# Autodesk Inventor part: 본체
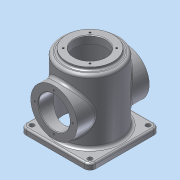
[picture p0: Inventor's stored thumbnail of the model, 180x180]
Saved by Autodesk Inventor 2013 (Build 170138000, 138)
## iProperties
Created: 2015-10
Part Number: 본체
Material: 알루미늄 6061
Document SubType Name: Modeling
Designer: dgall
Density: 2.71 g/cm^3
Mass: 987.031 g
Surface Area: 1039.62 cm^2
Volume: 364.218 cm^3
Author: dgall
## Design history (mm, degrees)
sketch "스케치1"
  geometry: L1 (-60, 60)-(60, 60); L2 (60, 60)-(60, -60); L3 (60, -60)-(-60, -60); L4 (-60, -60)-(-60, 60); L5 (-60, 60)-(60, -60); L6 (60, 60)-(-60, -60); C1 r 4 at (-50, 50); C2 r 4 at (50, 50); C3 r 4 at (50, -50); C4 r 4 at (-50, -50); 1 further point
  constraints: 12 end point, 4 centre point, 3 equal radius, 2 horizontal alignment, 2 midpoint, 2 parallel, 2 perpendicular, 2 vertical alignment, 1 horizontal
  dimensions: "d0" = 120 distance of L2.end L3.end; "d1" = 8 diameter of C1; "d2" = 100 distance of C2.centre C1.centre; "d3" = 50 horizontal distance of point (0, 0) C1.centre; "d4" = 100 distance of C3.centre C2.centre; "d5" = 50 horizontal distance of point (0, 0) C3.centre
extrude "돌출1" new body sketch "스케치1" distance "d6" = 10; taper "d7" = 0 deg
sketch "스케치2"
  geometry: C1 r 50 at (0, 0); C2 r 27 at (0, 0); 1 further point
  constraints: 2 centre point, 2 coincident
  dimensions: "d8" = 100 diameter of C1; "d9" = 54 diameter of C2
extrude "돌출2" join sketch "스케치2" distance "d10" = 115; taper "d11" = 0 deg
sketch "스케치4"
  geometry: C1 r 45 at (0, 0); 1 further point
  constraints: 1 centre point, 1 coincident
  dimensions: "d25" = 90 diameter of C1
extrude "돌출4" cut sketch "스케치4" distance "d26" = 112; taper "d27" = 0 deg
sketch "스케치5"
  geometry: C1 r 50 at (0, 0) reference; C2 r 50 at (0, 0); C3 r 40 at (0, 0)
  constraints: 2 centre point, 2 coincident
  dimensions: "d28" = 100 diameter of C2; "d29" = 80 diameter of C3
extrude "돌출5" cut sketch "스케치5" distance "d30" = 5; taper "d31" = 0 deg
fillet "모깎기1" dims "d32" = 10
sketch "스케치6"
  geometry: C1 r 4 at (-50, 50); C2 r 4 at (50, 50); C3 r 4 at (50, -50); C4 r 4 at (-50, -50); A1 r 10 centre (-50, 50) between (-50, 60) and (-60, 50) reference; A2 r 10 centre (-50, -50) between (-60, -50) and (-50, -60) reference; A3 r 10 centre (50, -50) between (50, -60) and (60, -50) reference; A4 r 10 centre (50, 50) between (60, 50) and (50, 60) reference
  constraints: 4 centre point, 4 coincident, 1 equal radius
  dimensions: "d33" = 8 diameter of C1; "d34" = 8 diameter of C3; "d35" = 8 diameter of C4
hole "구멍2" sketch "스케치6" at (-50, -50), (50, 50), (50, -50), (-50, 50) diameter "d36" = 8; stored, may be unused: countersink angle "d40" = 90 deg, drill point angle "d42" = 118 deg; dims "d37" = 6, "d38" = 4, "d39" = 2, "d41" = 8
fillet "모깎기2" dims "d43" = 5
sketch "스케치7"
  geometry: L1 (0, 100)-(0, 0) reference; 3 further points
  constraints: 1 horizontal alignment, 1 midpoint, 1 other
  dimensions: "d44" = 70 distance of point (0, 50) point (-70, 50)
feature "엠보싱1" sketch "스케치7" dims "d0" = 120, "d27" = 0, "d45" = 0.5, "d46" = 0
hole "구멍3" diameter "d52" = 54; stored, may be unused: countersink angle "d56" = 90 deg, drill point angle "d58" = 118 deg; dims "d50" = 10, "d51" = 10, "d53" = 6, "d54" = 4, "d55" = 2, "d57" = 8
sketch "스케치9"
  geometry: L1 (0, 0)-(-32.5, 0); L2 (0, 0)-(-22.981, -22.981); C1 r 40 at (0, 0) reference; A1 r 32.5 centre (0, 0) between (-32.5, 0) and (-22.981, -22.981); 1 further point
  constraints: 4 end point, 2 coincident, 2 point on circle, 1 centre point, 1 horizontal
  dimensions: "d60" = 65 diameter of A1; "d61" = 45 deg angle of L1 L2
hole "구멍4" sketch "스케치9" at (-22.981, -22.981) diameter "d63" = 3.242; stored, may be unused: countersink angle "d67" = 90 deg, drill point angle "d69" = 118 deg; dims "d64" = 8, "d65" = 4, "d66" = 2, "d68" = 10
sketch "스케치8"
  geometry: C1 r 40 at (0, 60); C2 r 27 at (0, 60); 1 further point
  constraints: 2 centre point, 1 concentric, 1 vertical alignment
  dimensions: "d47" = 80 diameter of C1; "d48" = 54 diameter of C2; "d49" = 60 distance of point (0, 0) C1.centre
extrude "돌출6" join sketch "스케치8" stored distance "d73" = 124; taper "d74" = 0 deg
extrude "돌출7" cut sketch "스케치8" stored distance "d75" = 124; taper "d76" = 0 deg
fillet "모깎기4" dims "d77" = 5
sketch "스케치10"
  geometry: L1 (0, 0)-(0, -32.5); C1 r 40 at (0, 0) reference; 2 further points
  constraints: 2 end point, 1 coincident, 1 vertical
  dimensions: "d78" = 32.5 distance of L1.start L1.end
hole "구멍5" sketch "스케치10" at (0, -32.5) diameter "d79" = 3.242; stored, may be unused: countersink angle "d83" = 90 deg, drill point angle "d85" = 118 deg; dims "d80" = 8, "d81" = 4, "d82" = 2, "d84" = 10
sketch "스케치11"
  geometry: L1 (0, 0)-(0, 32.5); C1 r 40 at (0, 0) reference; 2 further points
  constraints: 2 end point, 1 coincident, 1 vertical
  dimensions: "d89" = 32.5 distance of L1.start L1.end
hole "구멍6" sketch "스케치11" at (0, 32.5) diameter "d90" = 3.242; stored, may be unused: countersink angle "d94" = 90 deg, drill point angle "d96" = 118 deg; dims "d91" = 8, "d92" = 4, "d93" = 2, "d95" = 10
extrude "돌출8" cut sketch "스케치4" distance "d100" = 112; taper "d101" = 0 deg
fillet "모깎기3" dims "d59" = 3
chamfer "모따기1" distance "d102" = 1; stored, may be unused: second distance "d103" = 2, angle "d104" = 45 deg
chamfer "모따기2" distance "d105" = 1; stored, may be unused: second distance "d106" = 2, angle "d107" = 45 deg
chamfer "모따기3" distance "d108" = 1; stored, may be unused: second distance "d109" = 2, angle "d110" = 45 deg
chamfer "모따기4" distance "d111" = 3; stored, may be unused: second distance "d112" = 2, angle "d113" = 45 deg
fillet "모깎기5" dims "d114" = 3
node "솔리드1"
pattern_circular "원형 패턴1" dims angle "d71" = 360 deg
pattern_circular "원형 패턴2" dims angle "d87" = 360 deg
pattern_circular "원형 패턴3" dims angle "d98" = 360 deg
